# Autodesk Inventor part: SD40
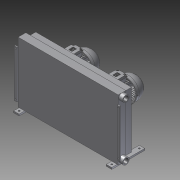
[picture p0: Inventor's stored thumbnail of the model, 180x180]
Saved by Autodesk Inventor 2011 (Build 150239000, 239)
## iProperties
Created: 2012-10
Part Number: SD40
Document SubType Name: Modeling
Designer: zazhorin
Density: 0.810682 g/cm^3
Mass: 50000 g
Surface Area: 26770.7 cm^2
Volume: 61676.5 cm^3
Author: zazhorin
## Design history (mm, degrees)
sketch "Эскиз1"
  geometry: L1 (0, 0)-(50, 0); L2 (50, 0)-(50, 300); L3 (50, 300)-(0, 300); L4 (0, 300)-(0, 0); L5 (840, 0)-(890, 0); L6 (890, 0)-(890, 300); L7 (890, 300)-(840, 300); L8 (840, 300)-(840, 0); C1 r 7 at (25, 25); C2 r 7 at (25, 275); C3 r 7 at (865, 275); C4 r 7 at (865, 25)
  constraints: 16 end point, 4 centre point, 4 parallel, 2 horizontal, 2 perpendicular
  dimensions: "d0" = 50 distance of L1.start L1.end; "d1" = 300 distance of L3.end L1.start; "d2" = 790 distance between parallel lines of L8 L2; "d3" = 50 distance of L5.start L5.end; "d4" = 300 distance of L5.end L6.end; "d5" = 25 distance from line of C1.centre L1; "d6" = 14 diameter of C1; "d7" = 25 distance from line of C1.centre L4; "d8" = 25 distance from line of L3 C2.centre; "d9" = 14 diameter of C2; "d10" = 25 distance from line of C2.centre L4; "d11" = 300 distance between parallel lines of L5 L3; "d12" = 25 distance from line of C3.centre L8; "d13" = 25 distance from line of C3.centre L7; "d14" = 14 diameter of C3; "d15" = 25 distance from line of C4.centre L8; "d16" = 25 distance from line of C4.centre L5; "d17" = 14 diameter of C4
extrude "Выдавливание1" new body sketch "Эскиз1" distance "d18" = 15; taper "d19" = 0 deg
node "РабПлоскость1"
sketch "Эскиз3"
  geometry: L1 (445, 550)-(924, 550); L2 (445, 275)-(1052.827, 275); L3 (924, 275)-(924, 490); L4 (924, 490)-(899, 490); L5 (899, 490)-(899, 275); L6 (924, 275)-(924, 60); L7 (899, 60)-(899, 275); L8 (924, 60)-(899, 60); L9 (-34, 275)-(-34, 60); L10 (-9, 60)-(-9, 275); L11 (-34, 60)-(-9, 60); L12 (-34, 275)-(-34, 490); L13 (-9, 490)-(-9, 275); L14 (-34, 490)-(-9, 490); L15 (890, 0)-(0, 0); L16 (0, 0)-(50, 0) reference; L17 (445, 0)-(445, 767.594); C1 r 5 at (911.5, 474); C2 r 5 at (911.5, 76); C3 r 5 at (-21.5, 76); C4 r 5 at (-21.5, 474)
  constraints: 32 end point, 4 centre point, 4 perpendicular, 3 symmetric about line, 2 point on line, 1 collinear, 1 midpoint, 1 parallel, 1 other
  dimensions: "d23" = 215 distance of L3.start L3.end; "d24" = 25 distance of L3.end L4.end; "d25" = 199 distance from line of C1.centre L2; "d26" = 12.5 distance from line of C1.centre L5; "d27" = 10 diameter of C1; "d35" = 0 distance from line of L1.end L3; "d36" = 479 distance between parallel lines of L17 L3; "d38" = 12.5 distance from line of L12 C4.centre; "d39" = 12.5 distance from line of C3.centre L9; "d40" = 479 distance between parallel lines of L12 L17
extrude "Выдавливание2" join sketch "Эскиз3" distance "d28" = 10; taper "d29" = 0 deg
sketch "Эскиз4"
  geometry: L1 (890, -15)-(-9, -15); L2 (-9, -15)-(-9, -490); L3 (899, -490)-(899, -565); L4 (899, -565)-(-9, -565); L5 (-9, -565)-(-9, -490); L6 (890, -15)-(899, -15); L7 (899, -15)-(899, -490); 1 further point
  constraints: 14 end point, 2 horizontal, 2 perpendicular, 1 parallel
  dimensions: "d30" = 75 distance of L4.end L2.end; "d31" = 908 distance of L3.end L4.end
extrude "Выдавливание3" join sketch "Эскиз4" distance "d32" = 70; taper "d33" = 0 deg
sketch "Эскиз5"
  geometry: L1 (0, 0)-(0, 70) reference; L2 (0, 0)-(550, 0); L3 (75, 0)-(0, 0) reference; L4 (505, 0)-(75, 0) reference; L5 (275, 0)-(275, -74.016); C1 r 30 at (30, 35); C2 r 30 at (520, 35); 1 further point
  constraints: 4 end point, 2 centre point, 1 collinear, 1 perpendicular, 1 point on line, 1 symmetric about line, 1 other
  dimensions: "d42" = 60 diameter of C1; "d43" = 245 distance from line of C1.centre L5
extrude "Выдавливание4" join sketch "Эскиз5" distance "d44" = 35; taper "d45" = 0 deg
sketch "Эскиз6"
  geometry: L1 (-9, -565)-(899, -565) reference; L2 (445, -565)-(445, -485.449); L3 (672, -511)-(218, -511); L4 (672, -69)-(218, -69); A1 r 221 centre (672, -290) between (672, -511) and (672, -69); A2 r 221 centre (218, -290) between (218, -69) and (218, -511); 1 further point
  constraints: 6 end point, 4 point on circle, 2 centre point, 2 tangent, 1 midpoint, 1 parallel, 1 perpendicular, 1 symmetric about line, 1 other
  dimensions: "d46" = 442 diameter of A1
extrude "Выдавливание5" join sketch "Эскиз6" distance "d47" = 360; taper "d48" = 0 deg
derived "111111111111.ipt"
feature "Переместить тело1"
sketch "Эскиз7"
  geometry: C1 r 125 at (0, 0) reference; C2 r 7.5 at (-76.014, -76.014) reference; C3 r 7.5 at (76.014, 76.014) reference; C4 r 7.5 at (76.014, -76.014) reference; C5 r 7.5 at (-76.014, 76.014) reference; A1 r 90 centre (0, 0) between (-89.809, -5.855) and (-5.855, -89.809) reference; A2 r 6 centre (-88.5, 0) between (-89.809, 5.855) and (-89.809, -5.855) reference; A3 r 90 centre (0, 0) between (-5.855, 89.809) and (-89.809, 5.855) reference; A4 r 6 centre (0, 88.5) between (5.855, 89.809) and (-5.855, 89.809) reference; A5 r 90 centre (0, 0) between (89.809, 5.855) and (5.855, 89.809) reference; A6 r 6 centre (88.5, 0) between (89.809, -5.855) and (89.809, 5.855) reference; A7 r 90 centre (0, 0) between (5.855, -89.809) and (89.809, -5.855) reference; A8 r 6 centre (0, -88.5) between (-5.855, -89.809) and (5.855, -89.809) reference; 1 further point
extrude "Выдавливание6" join sketch "Эскиз7" stored distance "d54" = 10; taper "d55" = 0 deg
feature "Переместить тело2"
sketch "Эскиз8"
  geometry: C1 r 125 at (0, 0) reference; C2 r 7.5 at (-76.014, -76.014) reference; C3 r 7.5 at (76.014, 76.014) reference; C4 r 7.5 at (76.014, -76.014) reference; C5 r 7.5 at (-76.014, 76.014) reference; A1 r 90 centre (0, 0) between (-89.809, -5.855) and (-5.855, -89.809) reference; A2 r 6 centre (-88.5, 0) between (-89.809, 5.855) and (-89.809, -5.855) reference; A3 r 90 centre (0, 0) between (-5.855, 89.809) and (-89.809, 5.855) reference; A4 r 6 centre (0, 88.5) between (5.855, 89.809) and (-5.855, 89.809) reference; A5 r 90 centre (0, 0) between (89.809, 5.855) and (5.855, 89.809) reference; A6 r 6 centre (88.5, 0) between (89.809, -5.855) and (89.809, 5.855) reference; A7 r 90 centre (0, 0) between (5.855, -89.809) and (89.809, -5.855) reference; A8 r 6 centre (0, -88.5) between (-5.855, -89.809) and (5.855, -89.809) reference; 1 further point
extrude "Выдавливание7" join sketch "Эскиз8" stored distance "d61" = 10; taper "d62" = 0 deg
sketch "Эскиз9"
  geometry: C1 r 125 at (626, -300) reference; C2 r 200 at (626, -300); C3 r 14.8 at (226, -300) reference; C4 r 200 at (226, -300); 1 further point
  constraints: 2 centre point, 2 coincident
  dimensions: "d63" = 400 diameter of C2; "d64" = 400 diameter of C4
extrude "Выдавливание8" join sketch "Эскиз9" distance "d65" = 100; taper "d66" = 0 deg
sketch "Эскиз10"
  geometry: 4 further points
  constraints: 1 coincident, 1 horizontal alignment
hole "Отверстие1" sketch "Эскиз10" at (0, 0) diameter "d67" = 44.845; stored, may be unused: countersink angle "d71" = 90 deg, drill point angle "d73" = 118 deg; dims "d68" = 45, "d69" = 4, "d70" = 2, "d72" = 50
sketch "Эскиз11"
  geometry: C1 r 30 at (0, 0) reference; 2 further points
  constraints: 1 coincident
hole "Отверстие2" sketch "Эскиз11" at (0, 0) diameter "d74" = 44.845; stored, may be unused: countersink angle "d78" = 90 deg, drill point angle "d80" = 118 deg; dims "d75" = 45, "d76" = 4, "d77" = 2, "d79" = 50
sketch "Эскиз12"
  geometry: L1 (934, -15)-(934, -75) reference; L2 (934, -45)-(804, -45); C1 r 17.5 at (804, -45); 2 further points
  constraints: 2 coincident, 2 end point, 1 centre point, 1 midpoint, 1 perpendicular
  dimensions: "d81" = 130 distance of L2.start L2.end; "d82" = 35 diameter of C1
extrude "Выдавливание9" join sketch "Эскиз12" distance "d83" = 15; taper "d84" = 0 deg
sketch "Эскиз13"
  geometry: C1 r 17.5 at (0, 0) reference; 2 further points
  constraints: 1 coincident
hole "Отверстие3" sketch "Эскиз13" at (0, 0) diameter "d85" = 18.631; stored, may be unused: countersink angle "d89" = 90 deg, drill point angle "d91" = 118 deg; dims "d86" = 45, "d87" = 4, "d88" = 2, "d90" = 50
fillet "Сопряжение1" dims "d92" = 10
sketch "Эскиз14"
  geometry: L1 (-9, -565)-(-9, -15) reference; L2 (899, -565)-(-9, -565) reference; L3 (899, -15)-(899, -565) reference; L4 (50, -15)-(840, -15) reference; L5 (879, -545)-(11, -545); L6 (11, -545)-(11, -35); L7 (11, -35)-(879, -35); L8 (879, -35)-(879, -545); 4 further points
  constraints: 8 end point, 2 horizontal alignment, 2 parallel, 1 horizontal, 1 perpendicular
  dimensions: "d93" = 20 distance between parallel lines of L8 L3; "d94" = 20 distance between parallel lines of L2 L5; "d95" = 20 distance between parallel lines of L6 L1; "d96" = 20 distance between parallel lines of L4 L7
extrude "Выдавливание10" join sketch "Эскиз14" distance "d97" = 70; taper "d98" = 0 deg
node "Твердое тело1"
feature "NONE::111111111111.ipt" dims "d49" = 10
tag "Элемент создания маркировки1"
feature "NONE::111111111111.ipt_1" dims "d56" = 10
tag "Элемент создания маркировки2"
node "Твердое тело2"
node "Твердое тело3"
other parameters: "d50" = -90 deg, "d52" = 297, "d57" = -90 deg, "d59" = 297
